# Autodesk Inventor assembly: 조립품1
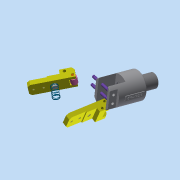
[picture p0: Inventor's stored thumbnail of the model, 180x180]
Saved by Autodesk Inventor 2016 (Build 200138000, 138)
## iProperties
Created: 2019-02
Part Number: 조립품1
Material: 일반
Document SubType Name: Assembly
Designer: 3sil_cad018
Author: 3sil_cad018
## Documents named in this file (8)
- C:\Users\3sil_cad018\Desktop\490207V1024\조립품1.iam
- C:\Users\3sil_cad018\Desktop\490207V1024\본체.ipt
- C:\Users\3sil_cad018\Desktop\490207V1024\부시.ipt
- C:\Users\3sil_cad018\Desktop\490207V1024\평행핀 6x28.ipt
- C:\Users\3sil_cad018\Desktop\490207V1024\핀.ipt
- C:\Users\3sil_cad018\Desktop\490207V1024\핑거.ipt
- C:\Users\3sil_cad018\Desktop\490207V1024\가이드핀.ipt
- C:\Users\3sil_cad018\Desktop\490207V1024\스프링.ipt
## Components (6 placed, 3 different names)
1. 핀:1
2. 핑거:1
3. 핀:2
4. 핑거:2
5. 가이드핀:1
6. 가이드핀:2
